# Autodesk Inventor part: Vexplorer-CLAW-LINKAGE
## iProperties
Created: 2007-10
Part Number: Vexplorer-CLAW-LINKAGE
Document SubType Name: Modeling
Material: ABS Plastic
Density: 1.06 g/cm^3
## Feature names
1. Base1
